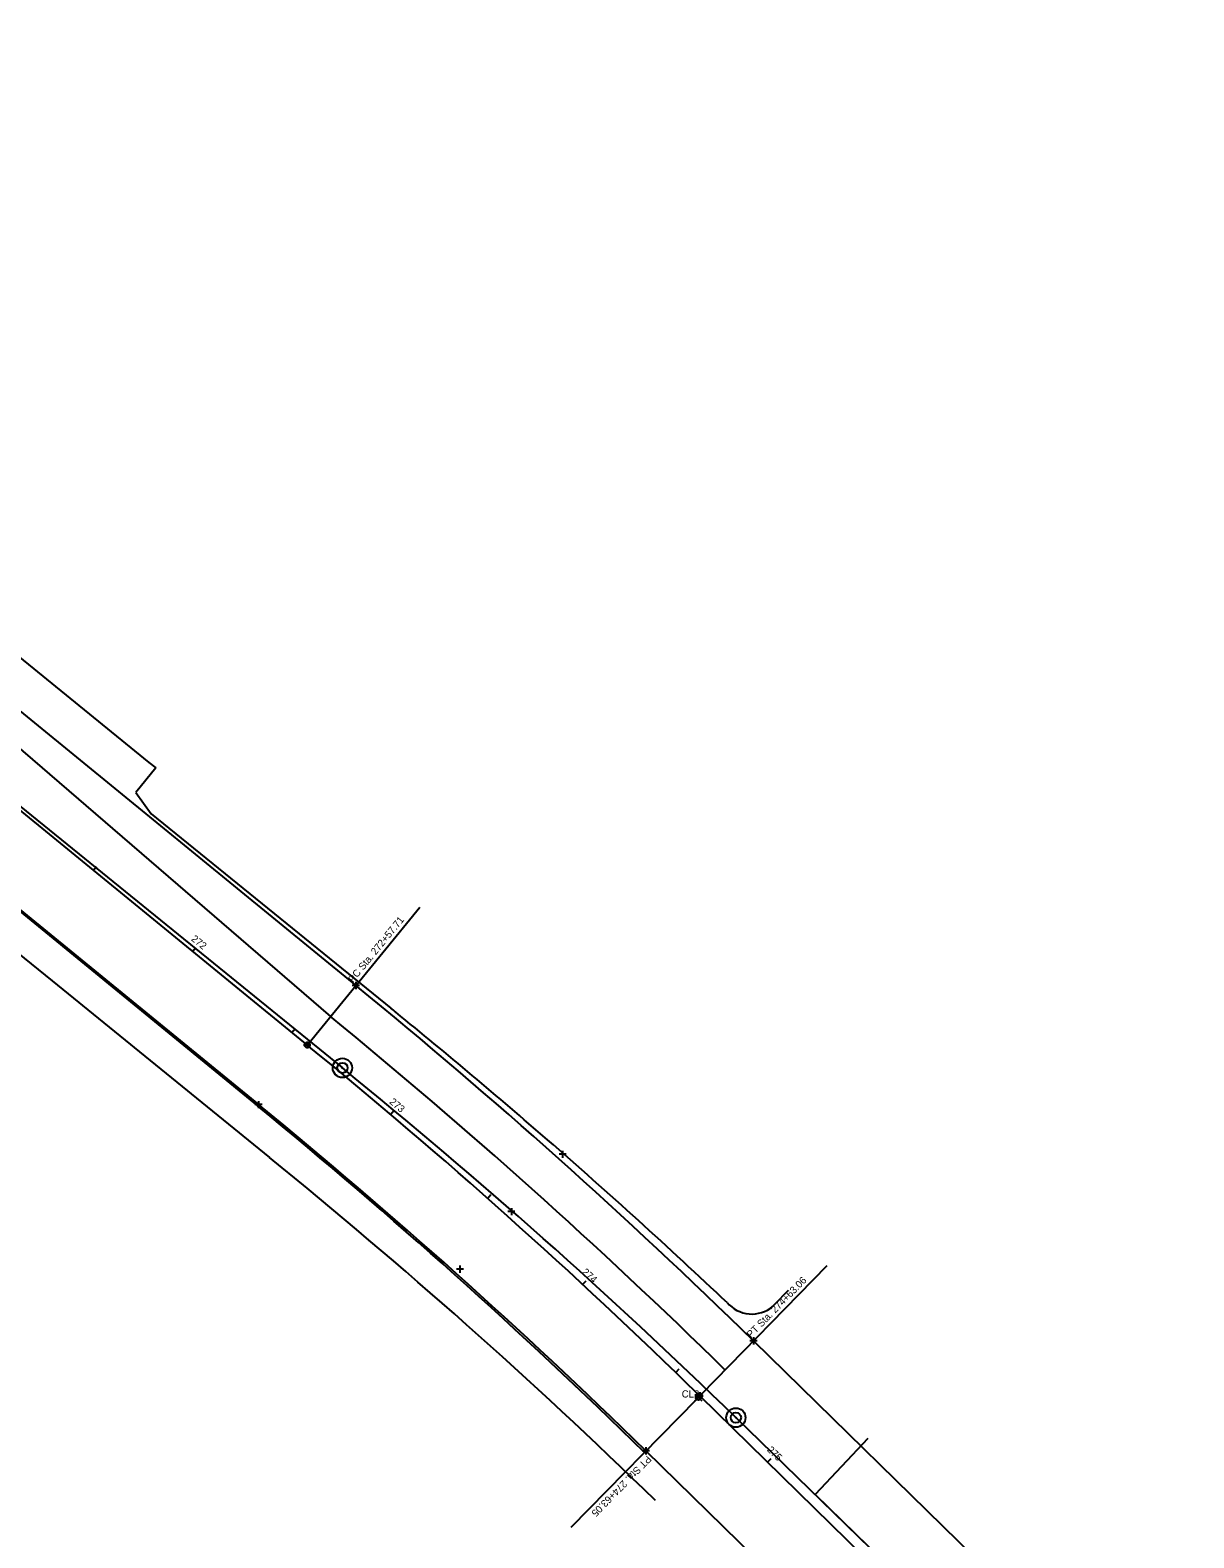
# Model space of a CAD drawing. Extents: x 1474076 to 1484331, y 375886 to 383395.
# Drawn here: x 1476924 to 1477378, y 382263 to 382851 of the extents above; entities that cross this region are included whole.
import ezdxf

# ---------------------------------------------------------------- set-up
doc = ezdxf.new("R2010")
doc.units = 0
for name, color, linetype in [('DV_X_Property_Line', 7, 'Continuous'), ('GK_Visualization', 7, 'Continuous'), ('PM_X_Channelizing_Line', 7, 'Continuous'), ('RW_X_Esmt_SH', 7, 'Continuous'), ('RW_X_Fee_RW', 7, 'Continuous'), ('SV_X_Mon_Cells_Found', 7, 'Continuous'), ('SV_X_Shot_Marker', 7, 'Continuous'), ('SV_X_Text_Elevation', 7, 'Continuous')]:
    doc.layers.add(name, color=color, linetype=linetype)

msp = doc.modelspace()

# ---------------------------------------------------------------- linework, layer by layer
at = {"layer": 'DV_X_Property_Line'}
for p, q in [((1477250.71, 382302.12), (1477230.14, 382280.28)), ((1477230.14, 382280.28), (1477344.34, 382169.23))]:
    msp.add_line(p, q, dxfattribs=at)
at = {"layer": 'GK_Visualization'}
for p, q in [((1477052.49, 382478.84), (1477049.69, 382478.84)), ((1477051.09, 382480.24), (1477051.09, 382477.44)), ((1477033.52, 382455.61), (1477030.72, 382455.61)), ((1477032.12, 382457.01), (1477032.12, 382454.21)), ((1477013.14, 382433.77), (1477013.14, 382430.97)), ((1477014.54, 382432.37), (1477011.74, 382432.37)), ((1477133.11, 382413.01), (1477130.31, 382413.01)), ((1477131.71, 382414.41), (1477131.71, 382411.61)), ((1477113.1, 382390.63), (1477110.3, 382390.63)), ((1477111.7, 382392.03), (1477111.7, 382389.23)), ((1477091.68, 382369.64), (1477091.68, 382366.84)), ((1477093.08, 382368.24), (1477090.28, 382368.24)), ((1477207.53, 382340.23), (1477204.73, 382340.23)), ((1477206.13, 382341.63), (1477206.13, 382338.83)), ((1477183.28, 382316.82), (1477185.95, 382319.49)), ((1477183.28, 382319.49), (1477185.95, 382316.82)), ((1477186.55, 382318.79), (1477183.75, 382318.79)), ((1477185.15, 382320.19), (1477185.15, 382317.39)), ((1477164.17, 382298.74), (1477164.17, 382295.94)), ((1477165.57, 382297.34), (1477162.77, 382297.34))]:
    msp.add_line(p, q, dxfattribs=at)
for radius, start, end in [(2321.93, 45.63561, 50.76903), (2291.93, 45.63561, 50.76903), (2261.93, 45.6356, 50.76902)]:
    msp.add_arc((1475582.59, 380680.27), radius, start, end, dxfattribs=at)
at = {"layer": 'PM_X_Channelizing_Line'}
for p, q in [((1476575.86, 382828.12), (1477045.83, 382446.68)), ((1476575.86, 382828.12), (1477032.12, 382455.61)), ((1476948.68, 382523.73), (1476949.94, 382525.28)), ((1477032.75, 382456.38), (1477076.05, 382509.41)), ((1476987.41, 382492.11), (1476988.68, 382493.65)), ((1477026.14, 382460.48), (1477027.41, 382462.03)), ((1477064.62, 382428.56), (1477065.92, 382430.09)), ((1477102.41, 382395.82), (1477103.73, 382397.31)), ((1477185.85, 382319.5), (1477234.82, 382369.57)), ((1477139.47, 382362.25), (1477140.83, 382363.72)), ((1477175.79, 382327.89), (1477177.18, 382329.33)), ((1477183.91, 382317.44), (1477134.91, 382267.44)), ((1477185.15, 382318.79), (1478151.68, 381373.49)), ((1477199.25, 382310.31), (1477450.25, 382066.25)), ((1477211.56, 382292.96), (1477212.96, 382294.39))]:
    msp.add_line(p, q, dxfattribs=at)
for centre in [(1477032.12, 382455.61), (1477184.61, 382318.16), (1477184.61, 382318.16), (1477185.15, 382318.79)]:
    msp.add_circle(centre, 1, dxfattribs=at)
for centre, radius, start, end in [((1475582.59, 380680.27), 2291.93, 45.63561, 50.76903), ((1475601.55, 380667.19), 2291.83, 45.80294, 50.93626)]:
    msp.add_arc(centre, radius, start, end, dxfattribs=at)
at = {"layer": 'RW_X_Esmt_SH'}
for p, q in [((1476594.83, 382851.36), (1477051.09, 382478.84)), ((1476594.86, 382851.34), (1477041.22, 382466.74)), ((1476556.86, 382804.9), (1477012.72, 382431.91)), ((1476556.89, 382804.88), (1477013.14, 382432.37)), ((1477206.13, 382340.23), (1478172.65, 381394.93)), ((1477164.17, 382297.34), (1478130.7, 381352.04))]:
    msp.add_line(p, q, dxfattribs=at)
for centre, radius, start, end in [((1475582.59, 380680.27), 2321.93, 45.63561, 50.76903), ((1475580.35, 380681.29), 2306.93, 45.57632, 50.70966), ((1475580.35, 380681.29), 2261.93, 45.57632, 50.70966), ((1475582.59, 380680.27), 2261.93, 45.6356, 50.76902)]:
    msp.add_arc(centre, radius, start, end, dxfattribs=at)
at = {"layer": 'RW_X_Fee_RW'}
for p, q in [((1476818.83, 382688.87), (1476970.41, 382565.84)), ((1476973.06, 382563.69), (1476965.23, 382554.05)), ((1476970.41, 382565.84), (1476973.06, 382563.69)), ((1476965.23, 382554.05), (1476971.3, 382545.8)), ((1476971.3, 382545.8), (1477064.73, 382469.97)), ((1476887.25, 382517.42), (1476932.65, 382480.58)), ((1476932.65, 382480.58), (1477017.47, 382411.74)), ((1477214.46, 382354.53), (1477219.7, 382360.02)), ((1477195.94, 382355.03), (1477196.68, 382354.34))]:
    msp.add_line(p, q, dxfattribs=at)
for centre, radius, start, end in [((1475601.55, 380667.19), 2321.83, 50.87456, 50.93631), ((1475601.55, 380667.19), 2321.83, 48.96581, 50.87456), ((1475601.55, 380667.19), 2321.83, 46.6308, 48.96581), ((1475601.55, 380667.19), 2246.83, 45.80178, 50.93631), ((1477205.47, 382363.21), 12.49, 225.26271, 316.00226)]:
    msp.add_arc(centre, radius, start, end, dxfattribs=at)
at = {"layer": 'SV_X_Mon_Cells_Found'}
for centre, radius in [((1477045.83, 382446.68), 3.75), ((1477045.83, 382446.68), 2), ((1477045.83, 382446.68), 0.075), ((1477045.83, 382446.68), 0.04), ((1477199.25, 382310.31), 3.75), ((1477199.25, 382310.31), 2), ((1477199.25, 382310.31), 0.075), ((1477199.25, 382310.31), 0.04)]:
    msp.add_circle(centre, radius, dxfattribs=at)

# ---------------------------------------------------------------- texts
at = {"layer": 'GK_Visualization'}
msp.add_text('CL3', height=2.8, dxfattribs=at).set_placement((1477178.13, 382318.16))
at = {"layer": 'PM_X_Channelizing_Line'}
for s, rotation, p in [('PC Sta. 272+57.71', 50.76971, (1477050, 382479.73)), ('272', 320.76971, (1476986.65, 382496.6)), ('273', 319.7119, (1477063.92, 382433.09)), ('274', 317.21201, (1477139, 382366.78)), ('PT Sta. 274+63.06', 45.63561, (1477205.13, 382341.21)), ('275', 315.63611, (1477211.19, 382297.51)), ('PT Sta. 274+63.05', 225.57632, (1477164.61, 382295.75))]:
    msp.add_text(s, height=2.8, rotation=rotation, dxfattribs=at).set_placement(p)
at = {"layer": 'SV_X_Shot_Marker'}
for s, p in [('52', (1477045.75, 382446.68)), ('53', (1477199.17, 382310.31))]:
    msp.add_text(s, height=0.06, dxfattribs=at).set_placement(p)
at = {"layer": 'SV_X_Text_Elevation'}
for p in [(1477045.53, 382446.62), (1477198.95, 382310.25)]:
    msp.add_text('840.00', height=0.06, dxfattribs=at).set_placement(p)

doc.saveas('drawing.dxf')
